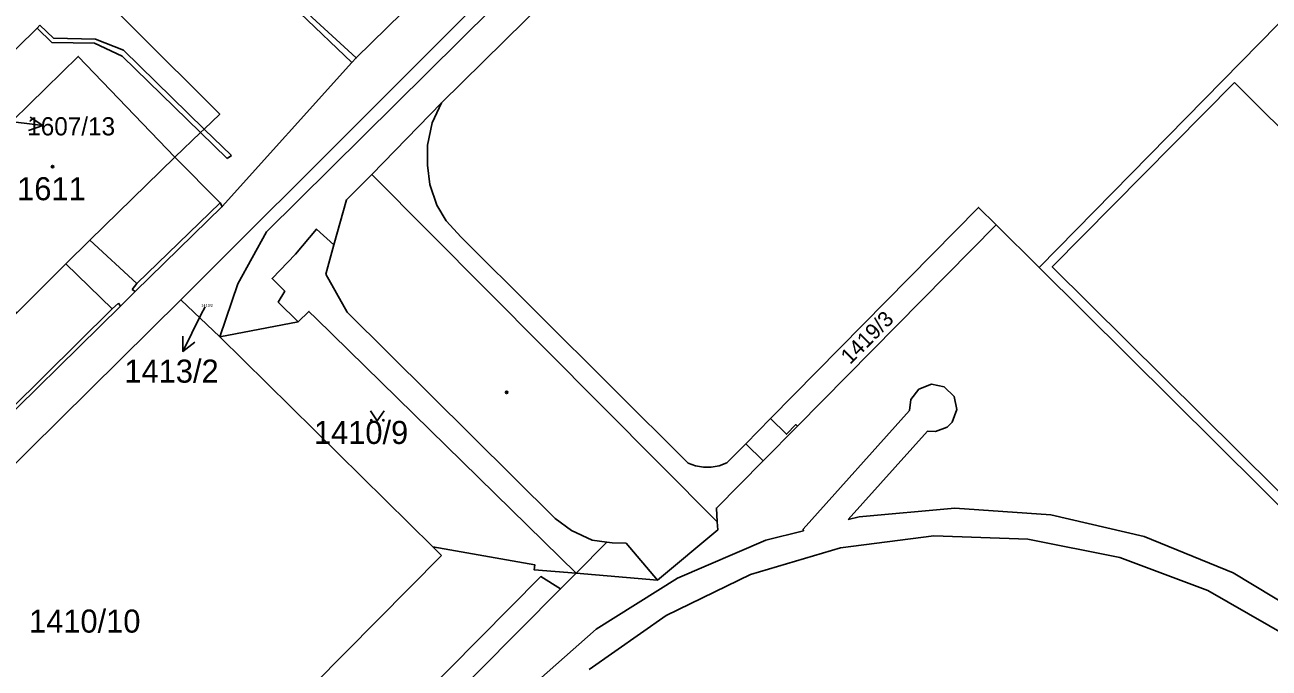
# Model space of a CAD drawing. Extents: x -598934 to -598196, y -1162208 to -1161502.
# Drawn here: x -598777.9 to -598686.2, y -1161742.9 to -1161695.5 of the extents above; entities that cross this region are included whole.
import ezdxf

# ---------------------------------------------------------------- set-up
doc = ezdxf.new("R2010")
doc.units = 0
for name, color, linetype in [('KN_CAR_KR', 7, 'Continuous'), ('KN_KULTURY', 7, 'Continuous'), ('KN_PARC_CIS_POM', 7, 'Continuous'), ('KN_PARC_CIS_POZ', 7, 'Continuous'), ('KN_PARC_CIS_STAV', 7, 'Continuous'), ('KN_PARC_PLOCHA', 7, 'Continuous'), ('PARC_C_SIPKA', 7, 'Continuous'), ('parcely_l', 7, 'Continuous')]:
    doc.layers.add(name, color=color, linetype=linetype)

msp = doc.modelspace()

# ---------------------------------------------------------------- linework, layer by layer
at = {"layer": 'KN_CAR_KR'}
for points in [[(-598777, -1161695.75), (-598787.26, -1161705.83)], [(-598777, -1161695.75), (-598776.79, -1161695.53)], [(-598775.92, -1161696.81), (-598777, -1161695.75)], [(-598776.79, -1161695.53), (-598775.79, -1161696.49)], [(-598775.79, -1161696.49), (-598772.7, -1161696.55)], [(-598772.7, -1161696.55), (-598770.63, -1161697.36)], [(-598775.92, -1161696.81), (-598772.76, -1161696.84)], [(-598772.76, -1161696.84), (-598770.74, -1161697.81)], [(-598770.63, -1161697.36), (-598764.68, -1161703.18)], [(-598764.95, -1161703.44), (-598770.74, -1161697.81)], [(-598680.22, -1161735.12), (-598702.18, -1161713.33), (-598688.73, -1161699.76)], [(-598688.73, -1161699.76), (-598666.78, -1161721.61)], [(-598747.89, -1161702.73), (-598747.18, -1161701.25)], [(-598747.89, -1161702.73), (-598748.23, -1161704.36)], [(-598762.98, -1161705.35), (-598764.95, -1161703.44)], [(-598764.68, -1161703.18), (-598762.68, -1161705.14)], [(-598748.22, -1161705.85), (-598748.23, -1161704.36)], [(-598762.68, -1161705.14), (-598762.98, -1161705.35)], [(-598748.22, -1161705.85), (-598748.05, -1161707.28)], [(-598726.87, -1161732.13), (-598752.32, -1161706.54)], [(-598748.05, -1161707.28), (-598747.54, -1161708.79)], [(-598763.51, -1161708.63), (-598769.65, -1161714.58)], [(-598747.54, -1161708.79), (-598746.85, -1161709.95)], [(-598745.73, -1161711.15), (-598746.85, -1161709.95)], [(-598769.65, -1161714.58), (-598773.11, -1161711.37)], [(-598729, -1161727.82), (-598745.73, -1161711.15)], [(-598755.12, -1161711.72), (-598755.72, -1161713.89)], [(-598774.88, -1161713.11), (-598771.46, -1161716.44)], [(-598754.14, -1161716.69), (-598755.72, -1161713.89)], [(-598703.13, -1161713.4), (-598680.2, -1161736.17)], [(-598769.65, -1161714.58), (-598769.98, -1161715)], [(-598769.98, -1161715), (-598769.76, -1161715.17)], [(-598771.46, -1161716.44), (-598781.48, -1161726.33)], [(-598771.01, -1161716.03), (-598771.46, -1161716.44)], [(-598770.86, -1161716.24), (-598771.01, -1161716.03)], [(-598738.82, -1161731.9), (-598754.14, -1161716.69)], [(-598712.6, -1161723.11), (-598712.02, -1161722.35)], [(-598712.02, -1161722.35), (-598711.08, -1161722)], [(-598711.08, -1161722), (-598710.14, -1161722.18)], [(-598710.14, -1161722.18), (-598709.4, -1161722.9)], [(-598712.7, -1161723.92), (-598712.6, -1161723.11)], [(-598709.4, -1161722.9), (-598709.2, -1161723.86)], [(-598720.54, -1161732.68), (-598712.7, -1161723.92)], [(-598709.2, -1161723.86), (-598709.56, -1161724.79)], [(-598722.94, -1161724.52), (-598724.77, -1161726.38)], [(-598709.91, -1161725.15), (-598710.79, -1161725.49)], [(-598709.56, -1161724.79), (-598709.91, -1161725.15)], [(-598711.37, -1161725.46), (-598717.22, -1161731.97)], [(-598710.79, -1161725.49), (-598711.37, -1161725.46)], [(-598724.77, -1161726.38), (-598726.17, -1161727.8)], [(-598723.49, -1161727.64), (-598724.77, -1161726.38)], [(-598729, -1161727.82), (-598728.46, -1161728.01)], [(-598726.17, -1161727.8), (-598726.73, -1161728)], [(-598727.87, -1161728.1), (-598728.46, -1161728.01)], [(-598727.87, -1161728.1), (-598727.31, -1161728.1)], [(-598727.31, -1161728.1), (-598726.73, -1161728)], [(-598709.36, -1161731.14), (-598716.41, -1161731.77)], [(-598702.29, -1161731.63), (-598709.36, -1161731.14)], [(-598738.82, -1161731.9), (-598737.62, -1161732.79)], [(-598717.22, -1161731.97), (-598716.41, -1161731.77)], [(-598695.39, -1161733.23), (-598702.29, -1161731.63)], [(-598737.62, -1161732.79), (-598736.09, -1161733.48)], [(-598723.28, -1161733.5), (-598720.51, -1161732.8)], [(-598720.51, -1161732.8), (-598720.54, -1161732.68)], [(-598710.9, -1161733.18), (-598717.77, -1161734.06)], [(-598703.98, -1161733.43), (-598710.9, -1161733.18)], [(-598688.83, -1161735.9), (-598695.39, -1161733.23)], [(-598747.18, -1161734.62), (-598747.83, -1161733.98)], [(-598737.26, -1161735.93), (-598735, -1161733.64)], [(-598736.09, -1161733.48), (-598735, -1161733.64)], [(-598735, -1161733.64), (-598734.62, -1161733.69)], [(-598734.62, -1161733.69), (-598733.58, -1161733.71)], [(-598733.58, -1161733.71), (-598731.28, -1161736.45)], [(-598723.28, -1161733.5), (-598729.79, -1161736.29)], [(-598717.77, -1161734.06), (-598724.41, -1161736.03)], [(-598697.19, -1161734.78), (-598703.98, -1161733.43)], [(-598766.09, -1161753.72), (-598747.18, -1161734.62)], [(-598690.71, -1161737.21), (-598697.19, -1161734.78)], [(-598724.41, -1161736.03), (-598730.64, -1161739.04)], [(-598682.76, -1161739.56), (-598688.83, -1161735.9)], [(-598729.79, -1161736.29), (-598735.78, -1161740.06)], [(-598684.7, -1161740.65), (-598690.71, -1161737.21)], [(-598730.64, -1161739.04), (-598736.31, -1161743.02)], [(-598735.78, -1161740.06), (-598741.11, -1161744.74)]]:
    msp.add_lwpolyline(points, dxfattribs=at)
at = {"layer": 'KN_KULTURY'}
msp.add_lwpolyline([(-598752.422, -1161723.952), (-598751.922, -1161724.702), (-598751.422, -1161723.952)], dxfattribs=at)
for centre, radius in [((-598775.86, -1161705.95), 0.09), ((-598775.86, -1161705.95), 0.0398), ((-598742.39, -1161722.6), 0.09), ((-598742.39, -1161722.6), 0.0398), ((-598752.372, -1161724.651), 0.05), ((-598751.473, -1161724.651), 0.05)]:
    msp.add_circle(centre, radius, dxfattribs=at)
at = {"layer": 'KN_PARC_PLOCHA'}
for points in [[(-598701.38, -1161646.66), (-598703.09, -1161648.71), (-598709.54, -1161654.96), (-598711.24, -1161656.61), (-598718.72, -1161663.97), (-598726.1, -1161671.1), (-598727.82, -1161672.87), (-598735.13, -1161679.98), (-598742.83, -1161687.52), (-598744.42, -1161689.04), (-598753.47, -1161697.94), (-598757.02, -1161694.7), (-598755.47, -1161693.03), (-598747.9, -1161685.6), (-598746.32, -1161683.99), (-598738.62, -1161676.44), (-598731.37, -1161669.32), (-598729.62, -1161667.55), (-598722.32, -1161660.32), (-598714.87, -1161653.1), (-598713.09, -1161651.31), (-598705.45, -1161643.89)], [(-598708.15, -1161659.2), (-598719.3, -1161670.3), (-598724.54, -1161675.5), (-598741.08, -1161691.91), (-598760.1, -1161710.77), (-598762.21, -1161714.59), (-598763.52, -1161718.51), (-598766.4, -1161715.78), (-598709.13, -1161658.56)], [(-598706.47, -1161660.3), (-598717.87, -1161671.81), (-598722.96, -1161676.93), (-598739.47, -1161693.64), (-598747.18, -1161701.25), (-598752.32, -1161706.54), (-598754.19, -1161708.41), (-598755.12, -1161711.72), (-598756.4, -1161710.56), (-598757.96, -1161712.41), (-598759.68, -1161714.2), (-598758.75, -1161715.13), (-598759.23, -1161715.94), (-598757.75, -1161717.39), (-598763.52, -1161718.51), (-598762.21, -1161714.59), (-598760.1, -1161710.77), (-598741.08, -1161691.91), (-598724.54, -1161675.5), (-598719.3, -1161670.3), (-598708.15, -1161659.2)], [(-598755.47, -1161693.03), (-598757.02, -1161694.7), (-598753.47, -1161697.94), (-598753.8, -1161698.27), (-598757.62, -1161694.64), (-598770.1, -1161683.17), (-598767.8, -1161680.81), (-598763.36, -1161685.12), (-598762.84, -1161684.49), (-598755.77, -1161692.74)], [(-598753.8, -1161698.27), (-598763.35, -1161708.9), (-598763.51, -1161708.63), (-598766.85, -1161705.26), (-598764.95, -1161703.44), (-598764.68, -1161703.18), (-598763.53, -1161702.08), (-598776.21, -1161689.42), (-598770.1, -1161683.17), (-598757.62, -1161694.64)], [(-598766.85, -1161705.26), (-598773.11, -1161711.37), (-598774.88, -1161713.11), (-598778.5, -1161716.73), (-598785.82, -1161709.42), (-598781.03, -1161704.79), (-598778.79, -1161702.55), (-598773.96, -1161697.83)], [(-598706.31, -1161710.25), (-598720.96, -1161725.08), (-598721.07, -1161724.97), (-598721.77, -1161725.68), (-598722.94, -1161724.52), (-598707.6, -1161708.96)], [(-598737.26, -1161735.93), (-598740.36, -1161735.68), (-598740.32, -1161735.3), (-598747.83, -1161733.98), (-598763.52, -1161718.51), (-598757.75, -1161717.39), (-598756.96, -1161716.63), (-598756.44, -1161717.14)], [(-598738.41, -1161737.09), (-598774.77, -1161773.75), (-598775.93, -1161772.6), (-598768.66, -1161765.26), (-598767.79, -1161755.43), (-598766.09, -1161753.72), (-598766.98, -1161763.58), (-598739.86, -1161736.18)]]:
    msp.add_lwpolyline(points, close=True, dxfattribs=at)
for points in [[(-598709.13, -1161658.56), (-598766.4, -1161715.78), (-598795.45, -1161744.48)], [(-598781.51, -1161726.72), (-598770.86, -1161716.24), (-598769.76, -1161715.17), (-598763.35, -1161708.9), (-598753.8, -1161698.27), (-598753.47, -1161697.94), (-598744.42, -1161689.04)], [(-598779.27, -1161692.54), (-598776.21, -1161689.42), (-598763.53, -1161702.08), (-598764.68, -1161703.18), (-598764.95, -1161703.44), (-598766.85, -1161705.26), (-598773.96, -1161697.83), (-598778.79, -1161702.55)], [(-598684.2, -1161694.1), (-598703.13, -1161713.4), (-598706.31, -1161710.25), (-598707.6, -1161708.96), (-598722.94, -1161724.52), (-598721.77, -1161725.68), (-598721.07, -1161724.97), (-598720.96, -1161725.08), (-598723.49, -1161727.64), (-598726.93, -1161731.13), (-598726.87, -1161732.13), (-598726.83, -1161732.74), (-598731.28, -1161736.45), (-598737.26, -1161735.93), (-598756.44, -1161717.14), (-598756.96, -1161716.63), (-598757.75, -1161717.39), (-598759.23, -1161715.94), (-598758.75, -1161715.13), (-598759.68, -1161714.2), (-598757.96, -1161712.41), (-598756.4, -1161710.56), (-598755.12, -1161711.72), (-598754.19, -1161708.41), (-598752.32, -1161706.54), (-598747.18, -1161701.25), (-598739.47, -1161693.64)], [(-598774.77, -1161773.75), (-598738.41, -1161737.09), (-598737.26, -1161735.93), (-598731.28, -1161736.45), (-598726.83, -1161732.74), (-598726.87, -1161732.13), (-598726.93, -1161731.13), (-598723.49, -1161727.64), (-598720.96, -1161725.08), (-598706.31, -1161710.25), (-598703.13, -1161713.4), (-598684.2, -1161694.1)], [(-598809.51, -1161747.26), (-598802.68, -1161740.64), (-598801.13, -1161739.01), (-598795.66, -1161733.55), (-598786.42, -1161724.52), (-598784.85, -1161722.95), (-598778.5, -1161716.73), (-598774.88, -1161713.11), (-598773.11, -1161711.37), (-598766.85, -1161705.26), (-598763.51, -1161708.63), (-598763.35, -1161708.9), (-598769.76, -1161715.17), (-598770.86, -1161716.24), (-598781.51, -1161726.72), (-598782.6, -1161727.85), (-598797.74, -1161742.83), (-598798.98, -1161744.03)], [(-598795.45, -1161744.48), (-598766.4, -1161715.78), (-598763.52, -1161718.51), (-598747.83, -1161733.98), (-598740.32, -1161735.3), (-598740.36, -1161735.68), (-598737.26, -1161735.93), (-598738.41, -1161737.09), (-598739.86, -1161736.18), (-598766.98, -1161763.58)]]:
    msp.add_lwpolyline(points, dxfattribs=at)
at = {"layer": 'PARC_C_SIPKA'}
for points in [[(-598779.9, -1161702.5), (-598779.56, -1161702.55), (-598776.583, -1161702.922)], [(-598777.513, -1161702.302), (-598776.583, -1161702.922), (-598777.637, -1161703.294)], [(-598764.62, -1161716.28), (-598764.92, -1161716.89), (-598766.265, -1161719.572)], [(-598765.37, -1161718.902), (-598766.265, -1161719.572), (-598766.264, -1161718.454)]]:
    msp.add_lwpolyline(points, dxfattribs=at)
at = {"layer": 'parcely_l'}
for points in [[(-598701.38, -1161646.66), (-598703.09, -1161648.71), (-598709.54, -1161654.96), (-598711.24, -1161656.61), (-598718.72, -1161663.97), (-598726.1, -1161671.1), (-598727.82, -1161672.87), (-598735.13, -1161679.98), (-598742.83, -1161687.52), (-598744.42, -1161689.04), (-598753.47, -1161697.94)], [(-598766.4, -1161715.78), (-598709.13, -1161658.56), (-598708.15, -1161659.2)], [(-598763.52, -1161718.51), (-598762.21, -1161714.59), (-598760.1, -1161710.77), (-598741.08, -1161691.91), (-598724.54, -1161675.5), (-598719.3, -1161670.3), (-598708.15, -1161659.2)], [(-598706.47, -1161660.3), (-598717.87, -1161671.81), (-598722.96, -1161676.93), (-598739.47, -1161693.64), (-598747.18, -1161701.25), (-598752.32, -1161706.54), (-598754.19, -1161708.41), (-598755.12, -1161711.72), (-598756.4, -1161710.56), (-598757.96, -1161712.41), (-598759.68, -1161714.2), (-598758.75, -1161715.13), (-598759.23, -1161715.94), (-598757.75, -1161717.39)], [(-598770.1, -1161683.17), (-598757.62, -1161694.64), (-598753.8, -1161698.27)], [(-598776.21, -1161689.42), (-598763.53, -1161702.08), (-598764.68, -1161703.18), (-598764.95, -1161703.44), (-598766.85, -1161705.26)], [(-598753.47, -1161697.94), (-598757.02, -1161694.7), (-598755.47, -1161693.03)], [(-598706.31, -1161710.25), (-598703.13, -1161713.4), (-598684.2, -1161694.1)], [(-598766.85, -1161705.26), (-598773.96, -1161697.83), (-598778.79, -1161702.55)], [(-598753.8, -1161698.27), (-598763.35, -1161708.9)], [(-598753.8, -1161698.27), (-598753.47, -1161697.94)], [(-598766.85, -1161705.26), (-598773.11, -1161711.37), (-598774.88, -1161713.11), (-598778.5, -1161716.73)], [(-598763.35, -1161708.9), (-598763.51, -1161708.63), (-598766.85, -1161705.26)], [(-598814.73, -1161756.78), (-598813.03, -1161756.71), (-598812.12, -1161756.49), (-598811.2, -1161755.89), (-598809.85, -1161754.77), (-598798.98, -1161744.03), (-598797.74, -1161742.83), (-598782.6, -1161727.85), (-598781.51, -1161726.72), (-598770.86, -1161716.24), (-598769.76, -1161715.17), (-598763.35, -1161708.9)], [(-598720.96, -1161725.08), (-598721.07, -1161724.97), (-598721.77, -1161725.68), (-598722.94, -1161724.52), (-598707.6, -1161708.96), (-598706.31, -1161710.25)], [(-598706.31, -1161710.25), (-598720.96, -1161725.08)], [(-598812.32, -1161761.04), (-598811.15, -1161760.23), (-598795.45, -1161744.48), (-598766.4, -1161715.78)], [(-598766.4, -1161715.78), (-598763.52, -1161718.51)], [(-598757.75, -1161717.39), (-598756.96, -1161716.63), (-598756.44, -1161717.14), (-598737.26, -1161735.93)], [(-598763.52, -1161718.51), (-598757.75, -1161717.39)], [(-598763.52, -1161718.51), (-598747.83, -1161733.98), (-598740.32, -1161735.3), (-598740.36, -1161735.68), (-598737.26, -1161735.93)], [(-598737.26, -1161735.93), (-598731.28, -1161736.45), (-598726.83, -1161732.74), (-598726.87, -1161732.13), (-598726.93, -1161731.13), (-598723.49, -1161727.64), (-598720.96, -1161725.08)], [(-598738.41, -1161737.09), (-598739.86, -1161736.18), (-598766.98, -1161763.58), (-598766.09, -1161753.72), (-598767.79, -1161755.43), (-598768.66, -1161765.26), (-598775.93, -1161772.6), (-598774.77, -1161773.75)], [(-598737.26, -1161735.93), (-598738.41, -1161737.09)], [(-598738.41, -1161737.09), (-598774.77, -1161773.75)]]:
    msp.add_lwpolyline(points, dxfattribs=at)

# ---------------------------------------------------------------- texts
at = {"layer": 'KN_PARC_CIS_POM'}
msp.add_text('1413/2', height=0.2, dxfattribs=at).set_placement((-598764.887, -1161716.28))
at = {"layer": 'KN_PARC_CIS_POZ'}
msp.add_text('1419/3', height=1.14, rotation=45, dxfattribs=at).set_placement((-598717.075, -1161720.595))
for s, p in [('1413/2', (-598770.567, -1161721.88)), ('1410/9', (-598756.597, -1161726.4)), ('1410/10', (-598777.597, -1161740.31))]:
    msp.add_text(s, height=1.7, dxfattribs=at).set_placement(p)
at = {"layer": 'KN_PARC_CIS_STAV'}
for s, height, p in [('1607/13', 1.34, (-598777.727, -1161703.65)), ('1611', 1.7, (-598778.472, -1161708.43))]:
    msp.add_text(s, height=height, dxfattribs=at).set_placement(p)

doc.saveas('drawing.dxf')
